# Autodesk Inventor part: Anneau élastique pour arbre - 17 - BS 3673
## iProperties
Shininess: 64.0
Length Units: 11269
Angle Units: 11279
Time Units: 11290
Mass Units: 11283
Length Display Precision: 3
Angle Display Precision: 2
Compacted: True
Part Number: Anneau élastique pour arbre - 17 - BS 3673
Document SubType Name: Modeling
Created: 2005-02
Material: Par défaut
Designer: LEGERET Philippe
Catalog Web Link: www.traceparts.com
Description: Anneau élastique pour arbre Ø17 - BS 3673
Density: 0.0
Volumn: 0.0
Area: 0.0
PropertySet Name: Model Information
Control State: 0
Master: False
Checked Out: False
Author: Trace Parts S.A.
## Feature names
1. Base1
